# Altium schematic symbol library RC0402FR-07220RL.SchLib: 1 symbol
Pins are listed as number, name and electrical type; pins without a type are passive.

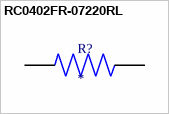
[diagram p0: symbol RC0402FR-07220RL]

## RC0402FR-07220RL
designator R?
220 Ohms Â±1% 0.063W, 1/16W Chip Resistor 0402 (1005 Metric) Moisture Resistant Thick Film; MF: Yageo; MP: RC0402FR-07220RL
footprint RESC1005X40N
pins: 1, 2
